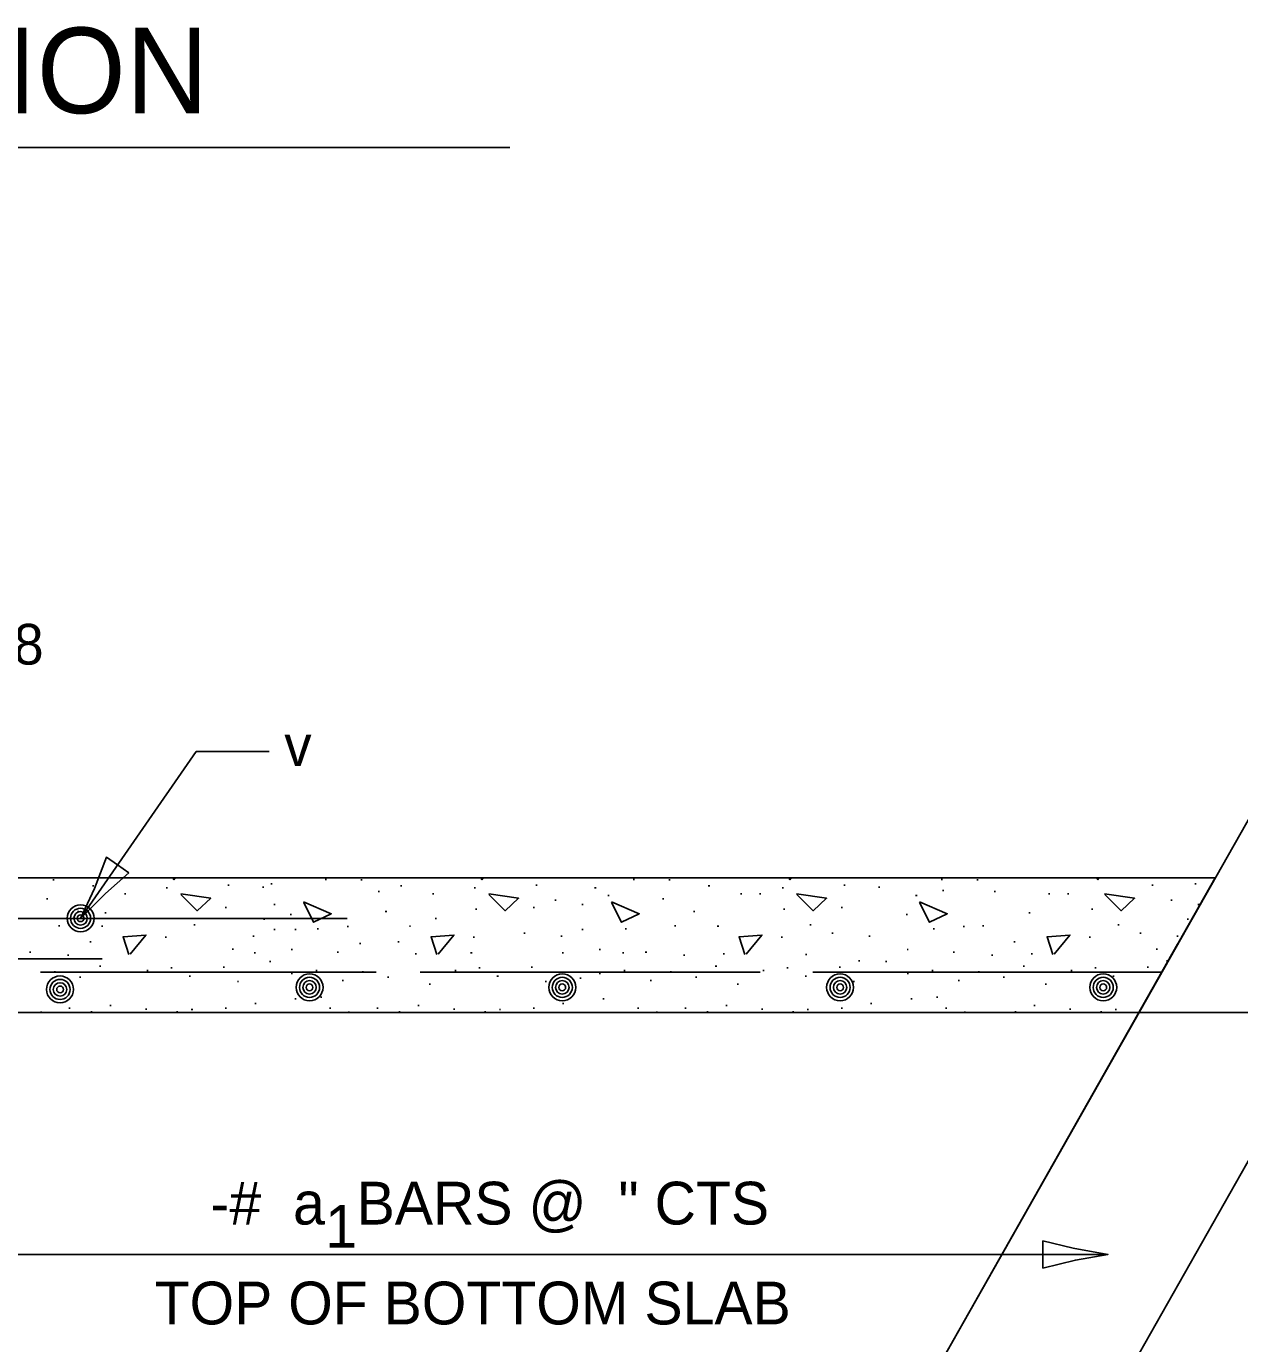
# Model space of a CAD drawing. Extents: x 2133490 to 2172050, y 2138301 to 2145980.
# Drawn here: x 2143604 to 2143774.1, y 2145069.8 to 2145254.4 of the extents above; entities that cross this region are included whole.
import ezdxf

# ---------------------------------------------------------------- set-up
doc = ezdxf.new("R2010")
doc.units = 0
for name, color, linetype in [('Level 40', 7, 'Continuous'), ('Level 63', 7, 'Continuous'), ('ROW_PR_Notes', 7, 'Continuous'), ('Topo_Bridge Structures', 7, 'Continuous')]:
    doc.layers.add(name, color=color, linetype=linetype)

msp = doc.modelspace()

# ---------------------------------------------------------------- linework, layer by layer
at = {"layer": 'Level 40'}
msp.add_line((2143841.23, 2145116.2), (2143759.94, 2145116.2), dxfattribs=at)
for centre, radius in [((2143611.61, 2145129.41), 1.89), ((2143611.61, 2145129.41), 1.41), ((2143611.61, 2145129.41), 0.943), ((2143611.61, 2145129.41), 0.472), ((2143608.73, 2145119.44), 1.89), ((2143608.73, 2145119.44), 1.41), ((2143608.73, 2145119.44), 0.943), ((2143643.7, 2145119.73), 1.89), ((2143643.7, 2145119.73), 1.41), ((2143643.7, 2145119.73), 0.943), ((2143643.7, 2145119.73), 0.472), ((2143679.12, 2145119.73), 1.89), ((2143679.12, 2145119.73), 1.41), ((2143679.12, 2145119.73), 0.943), ((2143679.12, 2145119.73), 0.472), ((2143718.06, 2145119.73), 1.89), ((2143718.06, 2145119.73), 1.41), ((2143718.06, 2145119.73), 0.943), ((2143718.06, 2145119.73), 0.472), ((2143754.94, 2145119.73), 1.89), ((2143754.94, 2145119.73), 1.41), ((2143754.94, 2145119.73), 0.943), ((2143754.94, 2145119.73), 0.472), ((2143608.73, 2145119.44), 0.472)]:
    msp.add_circle(centre, radius, dxfattribs=at)
at = {"layer": 'ROW_PR_Notes'}
for p, q in [((2143451.75, 2145237.43), (2143671.75, 2145237.43)), ((2143800.63, 2145188), (2143644.89, 2144913.16)), ((2143627.81, 2145152.77), (2143611.61, 2145129.4)), ((2143627.81, 2145152.77), (2143638.06, 2145152.77)), ((2143537.04, 2145135.06), (2143770.63, 2145135.06)), ((2143645.89, 2145134.87), (2143646.08, 2145134.87)), ((2143669.1, 2144955.89), (2143770.63, 2145135.06)), ((2143689.05, 2145134.87), (2143689.24, 2145134.87)), ((2143732.22, 2145134.87), (2143732.41, 2145134.87)), ((2143607.71, 2145134.8), (2143607.9, 2145134.8)), ((2143613.26, 2145133.95), (2143613.45, 2145133.95)), ((2143623.6, 2145133.67), (2143623.79, 2145133.67)), ((2143632.24, 2145134.07), (2143632.43, 2145134.07)), ((2143637.1, 2145133.75), (2143637.29, 2145133.75)), ((2143638.27, 2145134.24), (2143638.46, 2145134.24)), ((2143650.88, 2145134.8), (2143651.06, 2145134.8)), ((2143653.31, 2145133.18), (2143653.5, 2145133.18)), ((2143656.43, 2145133.95), (2143656.62, 2145133.95)), ((2143666.77, 2145133.67), (2143666.96, 2145133.67)), ((2143675.4, 2145134.07), (2143675.59, 2145134.07)), ((2143683.66, 2145133.67), (2143683.85, 2145133.67)), ((2143694.04, 2145134.8), (2143694.23, 2145134.8)), ((2143699.59, 2145133.95), (2143699.78, 2145133.95)), ((2143709.93, 2145133.67), (2143710.12, 2145133.67)), ((2143718.57, 2145134.07), (2143718.76, 2145134.07)), ((2143723.43, 2145133.75), (2143723.62, 2145133.75)), ((2143796.62, 2145133.12), (2143729.05, 2145013.87)), ((2143732.42, 2145133.3), (2143732.61, 2145133.3)), ((2143737.21, 2145134.8), (2143737.39, 2145134.8)), ((2143739.64, 2145133.18), (2143739.83, 2145133.18)), ((2143761.73, 2145134.07), (2143761.92, 2145134.07)), ((2143767.76, 2145134.24), (2143767.95, 2145134.24)), ((2143606.82, 2145132.13), (2143607.01, 2145132.13)), ((2143617.77, 2145132.86), (2143617.96, 2145132.86)), ((2143638.71, 2145131.36), (2143638.9, 2145131.36)), ((2143660.93, 2145132.86), (2143661.12, 2145132.86)), ((2143678.08, 2145131.97), (2143678.27, 2145131.97)), ((2143681.88, 2145131.36), (2143682.07, 2145131.36)), ((2143685.49, 2145132.61), (2143685.67, 2145132.61)), ((2143693.15, 2145132.13), (2143693.34, 2145132.13)), ((2143704.1, 2145132.86), (2143704.28, 2145132.86)), ((2143706.77, 2145132.86), (2143706.96, 2145132.86)), ((2143728.65, 2145132.61), (2143728.84, 2145132.61)), ((2143747.26, 2145132.86), (2143747.45, 2145132.86)), ((2143749.94, 2145132.86), (2143750.12, 2145132.86)), ((2143764.41, 2145131.97), (2143764.6, 2145131.97)), ((2143768.21, 2145131.36), (2143768.4, 2145131.36)), ((2143519.37, 2145129.4), (2143648.96, 2145129.4)), ((2143611.16, 2145130.35), (2143611.35, 2145130.35)), ((2143615.01, 2145130.18), (2143615.2, 2145130.18)), ((2143618.13, 2145129.37), (2143618.32, 2145129.37)), ((2143631.87, 2145130.91), (2143632.06, 2145130.91)), ((2143640.98, 2145129.94), (2143641.17, 2145129.94)), ((2143654.32, 2145130.35), (2143654.51, 2145130.35)), ((2143661.3, 2145129.37), (2143661.48, 2145129.37)), ((2143666.97, 2145130.67), (2143667.16, 2145130.67)), ((2143675.04, 2145130.91), (2143675.23, 2145130.91)), ((2143697.49, 2145130.35), (2143697.68, 2145130.35)), ((2143710.14, 2145130.67), (2143710.32, 2145130.67)), ((2143718.2, 2145130.91), (2143718.39, 2145130.91)), ((2143727.31, 2145129.94), (2143727.5, 2145129.94)), ((2143744.5, 2145130.18), (2143744.69, 2145130.18)), ((2143753.3, 2145130.67), (2143753.49, 2145130.67)), ((2143608.52, 2145128.36), (2143608.71, 2145128.36)), ((2143614.52, 2145128.32), (2143614.71, 2145128.32)), ((2143627.5, 2145128.48), (2143627.68, 2145128.48)), ((2143637.23, 2145129.29), (2143637.42, 2145129.29)), ((2143638.71, 2145127.83), (2143638.9, 2145127.83)), ((2143641.63, 2145127.83), (2143641.82, 2145127.83)), ((2143644.75, 2145127.91), (2143644.94, 2145127.91)), ((2143648.97, 2145128.24), (2143649.16, 2145128.24)), ((2143657.69, 2145128.32), (2143657.87, 2145128.32)), ((2143681.88, 2145127.83), (2143682.07, 2145127.83)), ((2143687.92, 2145127.91), (2143688.11, 2145127.91)), ((2143694.85, 2145128.36), (2143695.04, 2145128.36)), ((2143700.85, 2145128.32), (2143701.04, 2145128.32)), ((2143713.83, 2145128.48), (2143714.01, 2145128.48)), ((2143731.08, 2145127.91), (2143731.27, 2145127.91)), ((2143735.3, 2145128.24), (2143735.49, 2145128.24)), ((2143738.02, 2145128.36), (2143738.2, 2145128.36)), ((2143756.99, 2145128.48), (2143757.18, 2145128.48)), ((2143766.72, 2145129.29), (2143766.91, 2145129.29)), ((2143612.9, 2145126.13), (2143613.09, 2145126.13)), ((2143623.48, 2145126.78), (2143623.67, 2145126.78)), ((2143635.77, 2145126.9), (2143635.95, 2145126.9)), ((2143650.71, 2145125.89), (2143650.9, 2145125.89)), ((2143656.06, 2145126.13), (2143656.25, 2145126.13)), ((2143666.65, 2145126.78), (2143666.84, 2145126.78)), ((2143673.74, 2145127.34), (2143673.93, 2145127.34)), ((2143678.93, 2145126.9), (2143679.12, 2145126.9)), ((2143765.36, 2145125.77), (2143698.35, 2145007.51)), ((2143709.81, 2145126.78), (2143710, 2145126.78)), ((2143716.91, 2145127.34), (2143717.1, 2145127.34)), ((2143722.1, 2145126.9), (2143722.29, 2145126.9)), ((2143742.39, 2145126.13), (2143742.58, 2145126.13)), ((2143752.98, 2145126.78), (2143753.17, 2145126.78)), ((2143760.07, 2145127.34), (2143760.26, 2145127.34)), ((2143765.26, 2145126.9), (2143765.45, 2145126.9)), ((2143604.43, 2145124.67), (2143604.62, 2145124.67)), ((2143609.78, 2145124.22), (2143609.97, 2145124.22)), ((2143632.85, 2145125.08), (2143633.04, 2145125.08)), ((2143635.93, 2145124.59), (2143636.12, 2145124.59)), ((2143641.11, 2145125.03), (2143641.29, 2145125.03)), ((2143647.59, 2145124.67), (2143647.78, 2145124.67)), ((2143658.5, 2145124.43), (2143658.69, 2145124.43)), ((2143666.28, 2145124.59), (2143666.47, 2145124.59)), ((2143679.09, 2145124.59), (2143679.28, 2145124.59)), ((2143684.27, 2145125.03), (2143684.46, 2145125.03)), ((2143687.55, 2145124.59), (2143687.74, 2145124.59)), ((2143690.76, 2145124.67), (2143690.95, 2145124.67)), ((2143696.11, 2145124.22), (2143696.3, 2145124.22)), ((2143701.66, 2145124.43), (2143701.85, 2145124.43)), ((2143713.22, 2145124.35), (2143713.41, 2145124.35)), ((2143727.44, 2145125.03), (2143727.62, 2145125.03)), ((2143733.92, 2145124.67), (2143734.11, 2145124.67)), ((2143739.27, 2145124.22), (2143739.46, 2145124.22)), ((2143744.83, 2145124.43), (2143745.02, 2145124.43)), ((2143762.34, 2145125.08), (2143762.53, 2145125.08)), ((2143536.92, 2145123.75), (2143614.64, 2145123.75)), ((2143614.24, 2145122.72), (2143614.43, 2145122.72)), ((2143620.89, 2145122.07), (2143621.08, 2145122.07)), ((2143624.25, 2145122.48), (2143624.44, 2145122.48)), ((2143631.59, 2145122.56), (2143631.78, 2145122.56)), ((2143638.08, 2145123.37), (2143638.27, 2145123.37)), ((2143644.59, 2145122.07), (2143644.78, 2145122.07)), ((2143664.05, 2145122.07), (2143664.24, 2145122.07)), ((2143667.42, 2145122.48), (2143667.61, 2145122.48)), ((2143674.76, 2145122.56), (2143674.95, 2145122.56)), ((2143687.76, 2145122.07), (2143687.94, 2145122.07)), ((2143700.57, 2145122.72), (2143700.76, 2145122.72)), ((2143707.22, 2145122.07), (2143707.4, 2145122.07)), ((2143710.58, 2145122.48), (2143710.77, 2145122.48)), ((2143717.92, 2145122.56), (2143718.11, 2145122.56)), ((2143720.64, 2145123.45), (2143720.82, 2145123.45)), ((2143724.41, 2145123.37), (2143724.6, 2145123.37)), ((2143730.92, 2145122.07), (2143731.11, 2145122.07)), ((2143743.73, 2145122.72), (2143743.92, 2145122.72)), ((2143750.38, 2145122.07), (2143750.57, 2145122.07)), ((2143753.75, 2145122.48), (2143753.94, 2145122.48)), ((2143761.09, 2145122.56), (2143761.27, 2145122.56)), ((2143763.8, 2145123.45), (2143763.99, 2145123.45)), ((2143605.99, 2145121.86), (2143653.03, 2145121.86)), ((2143607.91, 2145121.91), (2143608.1, 2145121.91)), ((2143611.44, 2145121.18), (2143611.63, 2145121.18)), ((2143626.81, 2145121.3), (2143627, 2145121.3)), ((2143633.58, 2145120.53), (2143633.76, 2145120.53)), ((2143641.14, 2145121.67), (2143641.33, 2145121.67)), ((2143648.28, 2145120.7), (2143648.47, 2145120.7)), ((2143651.08, 2145121.91), (2143651.27, 2145121.91)), ((2143654.61, 2145121.18), (2143654.79, 2145121.18)), ((2143659.18, 2145121.86), (2143706.84, 2145121.86)), ((2143660.48, 2145120.17), (2143660.67, 2145120.17)), ((2143669.97, 2145121.3), (2143670.16, 2145121.3)), ((2143676.74, 2145120.53), (2143676.93, 2145120.53)), ((2143681.59, 2145121.02), (2143681.78, 2145121.02)), ((2143684.31, 2145121.67), (2143684.5, 2145121.67)), ((2143691.45, 2145120.7), (2143691.63, 2145120.7)), ((2143694.24, 2145121.91), (2143694.43, 2145121.91)), ((2143697.77, 2145121.18), (2143697.96, 2145121.18)), ((2143703.65, 2145120.17), (2143703.84, 2145120.17)), ((2143713.14, 2145121.3), (2143713.33, 2145121.3)), ((2143714.22, 2145121.86), (2143763.15, 2145121.86)), ((2143719.91, 2145120.53), (2143720.09, 2145120.53)), ((2143727.47, 2145121.67), (2143727.66, 2145121.67)), ((2143734.61, 2145120.7), (2143734.8, 2145120.7)), ((2143737.41, 2145121.91), (2143737.6, 2145121.91)), ((2143740.93, 2145121.18), (2143741.12, 2145121.18)), ((2143746.81, 2145120.17), (2143747, 2145120.17)), ((2143756.3, 2145121.3), (2143756.49, 2145121.3)), ((2143645.24, 2145118.34), (2143645.43, 2145118.34)), ((2143731.57, 2145118.34), (2143731.76, 2145118.34)), ((2143609.98, 2145116.8), (2143610.17, 2145116.8)), ((2143615.7, 2145117.21), (2143615.89, 2145117.21)), ((2143620.72, 2145116.68), (2143620.91, 2145116.68)), ((2143627.13, 2145116.64), (2143627.32, 2145116.64)), ((2143631.87, 2145116.8), (2143632.06, 2145116.8)), ((2143636.01, 2145117.49), (2143636.2, 2145117.49)), ((2143641.63, 2145118.1), (2143641.82, 2145118.1)), ((2143646.5, 2145116.8), (2143646.69, 2145116.8)), ((2143653.15, 2145116.8), (2143653.33, 2145116.8)), ((2143658.86, 2145117.21), (2143659.05, 2145117.21)), ((2143663.89, 2145116.68), (2143664.08, 2145116.68)), ((2143670.3, 2145116.64), (2143670.48, 2145116.64)), ((2143675.04, 2145116.8), (2143675.23, 2145116.8)), ((2143679.17, 2145117.49), (2143679.36, 2145117.49)), ((2143684.8, 2145118.1), (2143684.99, 2145118.1)), ((2143689.66, 2145116.8), (2143689.85, 2145116.8)), ((2143696.31, 2145116.8), (2143696.5, 2145116.8)), ((2143702.03, 2145117.21), (2143702.22, 2145117.21)), ((2143707.05, 2145116.68), (2143707.24, 2145116.68)), ((2143713.46, 2145116.64), (2143713.65, 2145116.64)), ((2143718.2, 2145116.8), (2143718.39, 2145116.8)), ((2143722.34, 2145117.49), (2143722.53, 2145117.49)), ((2143727.96, 2145118.1), (2143728.15, 2145118.1)), ((2143732.83, 2145116.8), (2143733.02, 2145116.8)), ((2143745.19, 2145117.21), (2143745.38, 2145117.21)), ((2143750.22, 2145116.68), (2143750.41, 2145116.68)), ((2143756.63, 2145116.64), (2143756.81, 2145116.64)), ((2143520.27, 2145116.2), (2143759.94, 2145116.2)), ((2143605.97, 2145116.24), (2143606.16, 2145116.24)), ((2143613.06, 2145116.32), (2143613.25, 2145116.32)), ((2143625.06, 2145116.32), (2143625.25, 2145116.32)), ((2143649.13, 2145116.24), (2143649.32, 2145116.24)), ((2143656.23, 2145116.32), (2143656.42, 2145116.32)), ((2143668.23, 2145116.32), (2143668.42, 2145116.32)), ((2143692.3, 2145116.24), (2143692.49, 2145116.24)), ((2143699.39, 2145116.32), (2143699.58, 2145116.32)), ((2143711.39, 2145116.32), (2143711.58, 2145116.32)), ((2143735.46, 2145116.24), (2143735.65, 2145116.24)), ((2143742.56, 2145116.32), (2143742.75, 2145116.32)), ((2143754.56, 2145116.32), (2143754.75, 2145116.32)), ((2143755.59, 2145082.3), (2143551.24, 2145082.3))]:
    msp.add_line(p, q, dxfattribs=at)
for points in [[(2143624.57, 2145135.06), (2143624.69, 2145134.8)], [(2143624.69, 2145134.8), (2143624.85, 2145135.06)], [(2143667.74, 2145135.06), (2143667.86, 2145134.8)], [(2143667.86, 2145134.8), (2143668.01, 2145135.06)], [(2143710.9, 2145135.06), (2143711.02, 2145134.8)], [(2143711.02, 2145134.8), (2143711.18, 2145135.06)], [(2143754.06, 2145135.06), (2143754.19, 2145134.8)], [(2143754.19, 2145134.8), (2143754.34, 2145135.06)], [(2143625.68, 2145132.73), (2143627.95, 2145130.46), (2143629.84, 2145132.21), (2143625.64, 2145132.82)], [(2143642.88, 2145131.64), (2143644.25, 2145128.86), (2143646.75, 2145130.04), (2143642.85, 2145131.7)], [(2143668.85, 2145132.73), (2143671.12, 2145130.46), (2143673, 2145132.21), (2143668.81, 2145132.82)], [(2143686.04, 2145131.64), (2143687.41, 2145128.86), (2143689.92, 2145130.04), (2143686.01, 2145131.7)], [(2143712.01, 2145132.73), (2143714.28, 2145130.46), (2143716.17, 2145132.21), (2143711.97, 2145132.82)], [(2143729.21, 2145131.64), (2143730.58, 2145128.86), (2143733.08, 2145130.04), (2143729.18, 2145131.7)], [(2143755.18, 2145132.73), (2143757.45, 2145130.46), (2143759.33, 2145132.21), (2143755.14, 2145132.82)], [(2143618.55, 2145124.37), (2143620.77, 2145127.06), (2143617.56, 2145126.82), (2143618.37, 2145124.32)], [(2143661.72, 2145124.37), (2143663.94, 2145127.06), (2143660.73, 2145126.82), (2143661.53, 2145124.32)], [(2143704.88, 2145124.37), (2143707.1, 2145127.06), (2143703.89, 2145126.82), (2143704.69, 2145124.32)], [(2143748.05, 2145124.37), (2143750.27, 2145127.06), (2143747.06, 2145126.82), (2143747.86, 2145124.32)]]:
    msp.add_lwpolyline(points, dxfattribs=at)
at = {"layer": 'Topo_Bridge Structures'}
for points in [[(2143618.36, 2145135.8), (2143616.8, 2145136.89), (2143615.23, 2145137.97), (2143613.56, 2145133.59), (2143611.61, 2145129.4), (2143615.1, 2145132.89)], [(2143746.49, 2145084.2), (2143746.49, 2145082.3), (2143746.49, 2145080.39), (2143751.04, 2145081.51), (2143755.59, 2145082.3), (2143750.74, 2145083.18)]]:
    msp.add_lwpolyline(points, close=True, dxfattribs=at)

# ---------------------------------------------------------------- texts
at = {"layer": 'Level 63'}
for s, height, p in [('HALF LONG SECTION', 12, (2143462.8, 2145242.24)), ('  -#  a  BARS @  " CTS', 6, (2143625.33, 2145086.49)), ('1', 6, (2143645.9, 2145083.25)), ('TOP OF BOTTOM SLAB', 6, (2143621.99, 2145072.49))]:
    msp.add_text(s, height=height, dxfattribs=at).set_placement(p)
at = {"layer": 'ROW_PR_Notes'}
for s, p in [('8', (2143602.19, 2145164.97)), ('v', (2143640.17, 2145150.76))]:
    msp.add_text(s, height=5.7, dxfattribs=at).set_placement(p)

doc.saveas('drawing.dxf')
